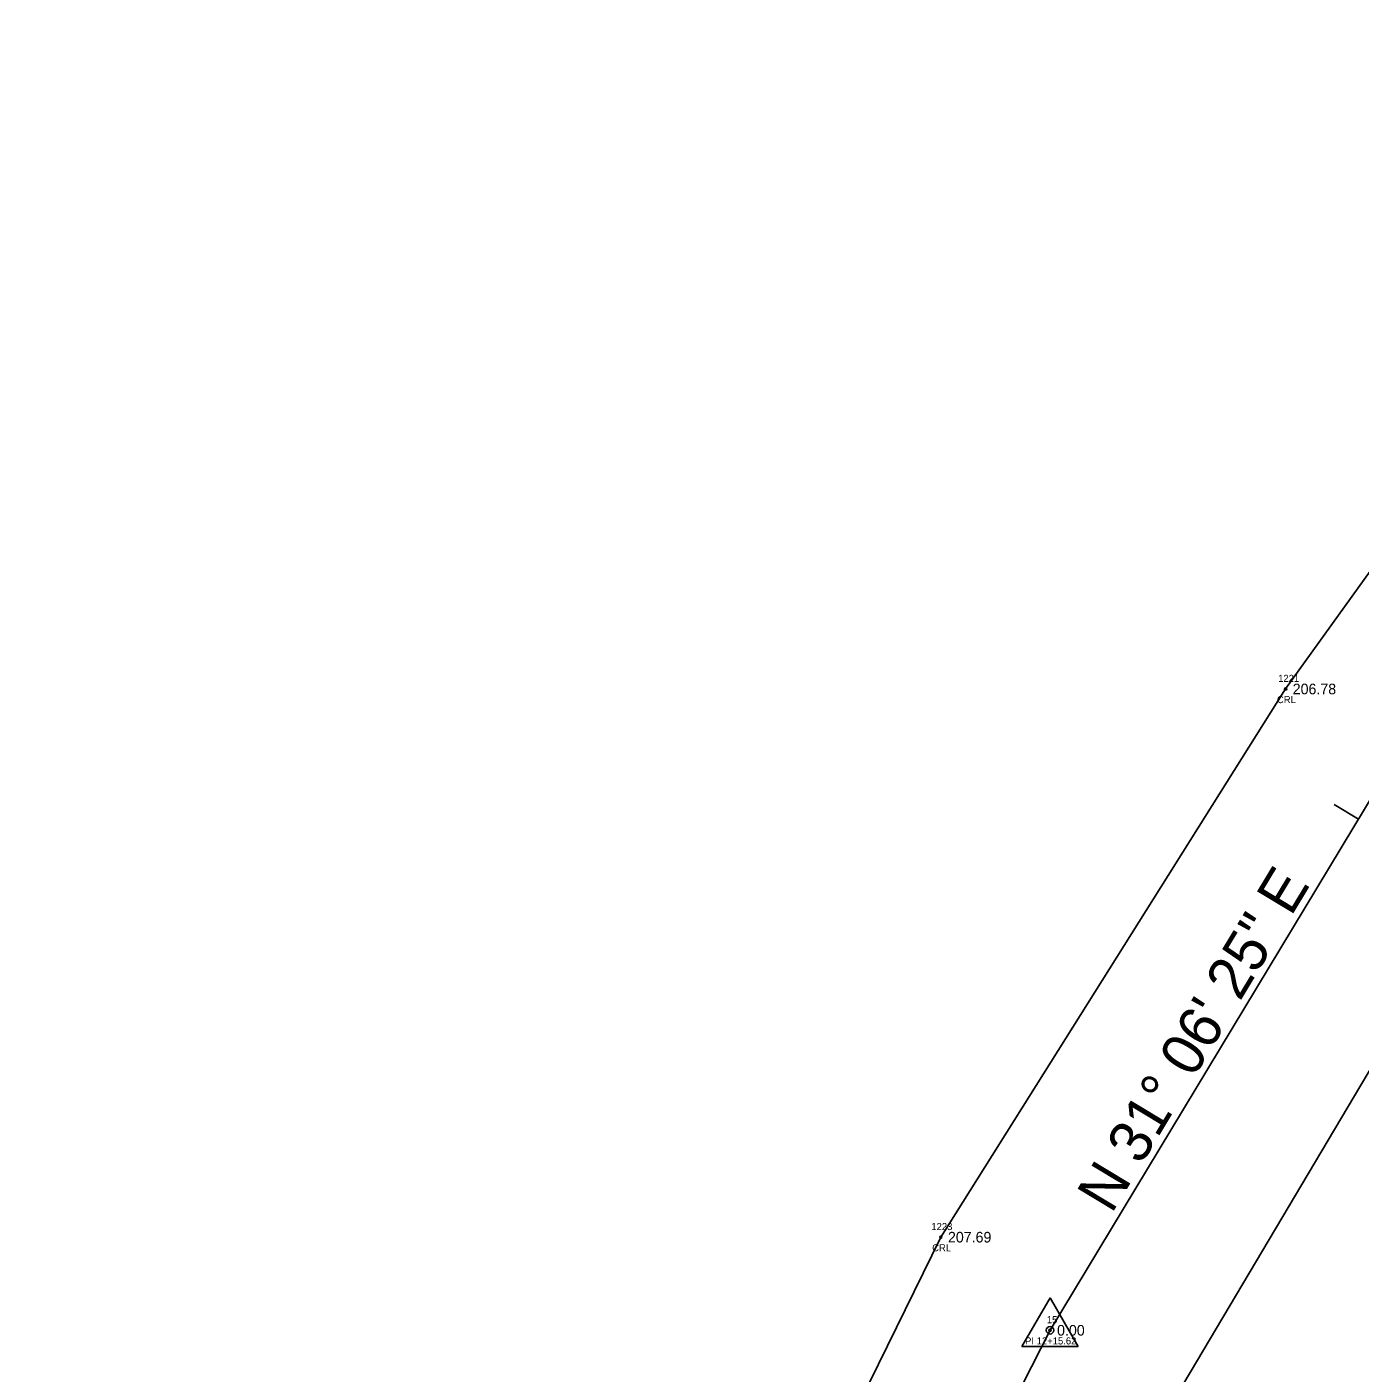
# Model space of a CAD drawing. Extents: x 2259948 to 2261336, y 1064647 to 1065986.
# Drawn here: x 2260488.2 to 2260676.5, y 1064832.3 to 1065022.5 of the extents above; entities that cross this region are included whole.
import ezdxf

# ---------------------------------------------------------------- set-up
doc = ezdxf.new("R2010")
doc.units = 0
for name, color, linetype in [('RD_EX_H2O', 7, 'Continuous'), ('RD_EX_H2O_txCode', 7, 'Continuous'), ('RD_EX_TX_H2O_ELEV', 7, 'Continuous'), ('RD_HC_Cl', 7, 'Continuous'), ('RD_HC_Data', 7, 'Continuous'), ('RD_HC_Data_Tic', 7, 'Continuous'), ('RD_HC_Survey_ELEV', 7, 'Continuous'), ('RD_HC_txCode', 7, 'Continuous'), ('RD_SMD_Locator', 7, 'Continuous')]:
    doc.layers.add(name, color=color, linetype=linetype)

msp = doc.modelspace()

# ---------------------------------------------------------------- linework, layer by layer
at = {"layer": 'RD_EX_H2O'}
for points in [[(2260766.96, 1065089.79), (2260769.94, 1065084.22), (2260769.59, 1065075.21), (2260766.59, 1065063.56), (2260718.2, 1065001.51), (2260666.03, 1064928.94), (2260617.31, 1064851.47), (2260573.34, 1064761.94), (2260536.11, 1064718.88), (2260488.15, 1064682.39)], [(2260814.11, 1065053.05), (2260812.59, 1065051.01), (2260806.25, 1065051.8), (2260750.48, 1064985.06), (2260697.06, 1064907.27), (2260648.8, 1064826.07), (2260606.38, 1064743.85), (2260584.89, 1064714.82), (2260586.34, 1064702.25), (2260547.45, 1064661.75), (2260541.67, 1064664.24), (2260523.34, 1064649.3)]]:
    msp.add_lwpolyline(points, dxfattribs=at)
at = {"layer": 'RD_HC_Cl'}
for p, q in [((2260632.73, 1064838.31), (2260680.74, 1064917.88)), ((2260589.28, 1064752.91), (2260632.73, 1064838.31))]:
    msp.add_line(p, q, dxfattribs=at)
at = {"layer": 'RD_HC_Data'}
for p, q in [((2260628.76, 1064836.02), (2260632.73, 1064842.9)), ((2260632.73, 1064842.9), (2260636.7, 1064836.02)), ((2260628.76, 1064836.02), (2260636.7, 1064836.02))]:
    msp.add_line(p, q, dxfattribs=at)
msp.add_circle((2260632.73, 1064838.31), 0.529, dxfattribs=at)
at = {"layer": 'RD_HC_Data_Tic'}
msp.add_line((2260676.32, 1064910.56), (2260672.9, 1064912.62), dxfattribs=at)
at = {"layer": 'RD_SMD_Locator'}
for centre in [(2260666.03, 1064928.94), (2260617.31, 1064851.47), (2260632.73, 1064838.31)]:
    msp.add_circle(centre, 0.15, dxfattribs=at)

# ---------------------------------------------------------------- texts
at = {"layer": 'RD_EX_H2O_txCode'}
for s, p in [('1221', (2260664.97, 1064929.94)), ('CRL', (2260664.8, 1064926.94)), ('1223', (2260615.96, 1064852.47)), ('CRL', (2260616.08, 1064849.47))]:
    msp.add_text(s, height=1, dxfattribs=at).set_placement(p)
at = {"layer": 'RD_EX_TX_H2O_ELEV'}
for s, p in [('206.78', (2260667.03, 1064928.19)), ('207.69', (2260618.31, 1064850.72))]:
    msp.add_text(s, height=1.5, dxfattribs=at).set_placement(p)
at = {"layer": 'RD_HC_Data'}
msp.add_text('N 31%%d 06\' 25" E', height=6, rotation=58.8929, dxfattribs=at).set_placement((2260641.43, 1064854.66))
at = {"layer": 'RD_HC_Survey_ELEV'}
msp.add_text('0.00', height=1.5, dxfattribs=at).set_placement((2260633.73, 1064837.56))
at = {"layer": 'RD_HC_txCode'}
for s, p in [('15', (2260632.28, 1064839.31)), ('PI 12+15.62', (2260629.21, 1064836.31))]:
    msp.add_text(s, height=1, dxfattribs=at).set_placement(p)

doc.saveas('drawing.dxf')
